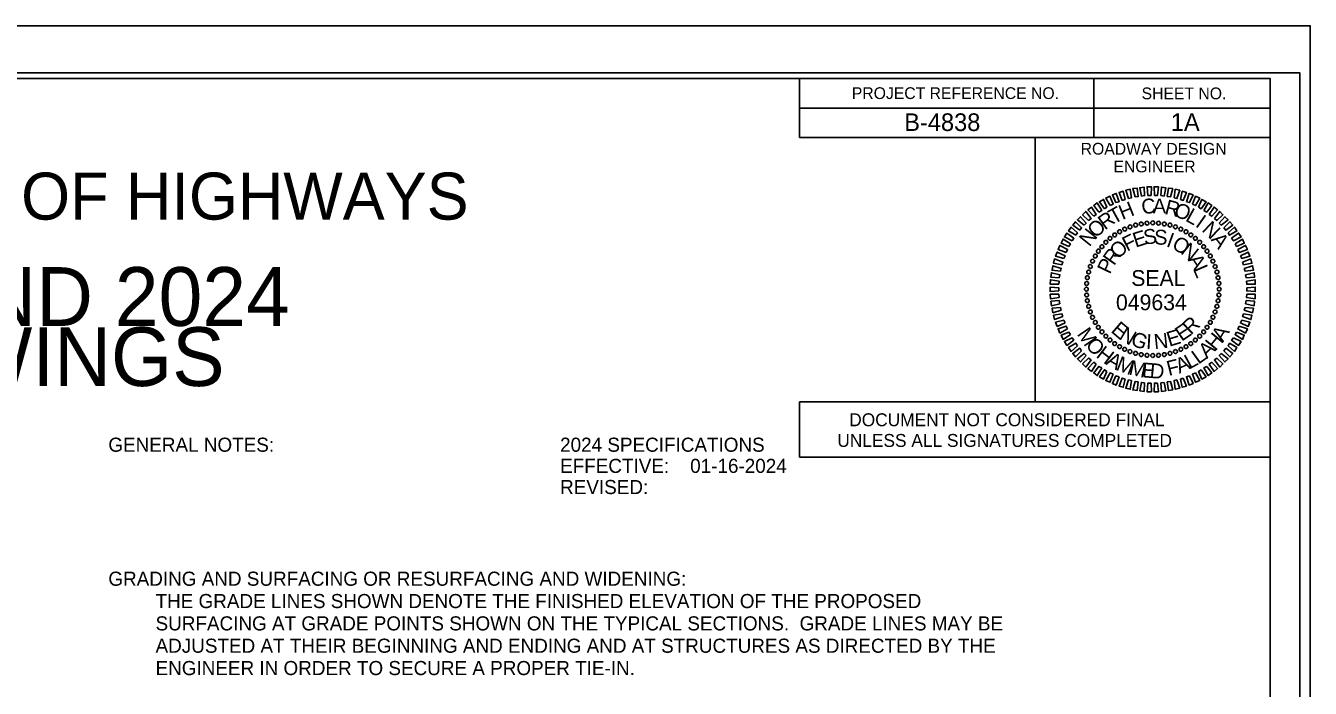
# Model space of a CAD drawing. Extents: x 775818 to 777502, y 889228 to 890323.
# Drawn here: x 776956 to 777502, y 890041 to 890323 of the extents above; entities that cross this region are included whole.
import ezdxf

# ---------------------------------------------------------------- set-up
doc = ezdxf.new("R2010")
doc.units = 0
for name, color, linetype in [('Default', 7, 'Continuous'), ('Sheet Border Standard 30in CELL', 7, 'Continuous'), ('Sheet Cutting Line CELL', 7, 'Continuous'), ('Sheet Data Field CELL', 7, 'Continuous'), ('Sheet Data Text CELL', 7, 'Continuous'), ('Sheet Plan CELL', 7, 'Continuous'), ('Sheet Plot Border Inside CELL', 7, 'Continuous'), ('Sheet Plot Border Outside CELL', 7, 'Continuous'), ('Sheet Professional Seal CELL', 7, 'Continuous'), ('Sheet Sticker Exception Certification CELL', 7, 'Continuous'), ('Sheet Symbology CELL', 7, 'Continuous')]:
    doc.layers.add(name, color=color, linetype=linetype)

# ---------------------------------------------------------------- blocks, each defined once
blk = doc.blocks.new('POINT_DISPLAY')
at = {"layer": 'Default'}
blk.add_line((0, 0), (0, 0), dxfattribs=at)

msp = doc.modelspace()

# ---------------------------------------------------------------- linework, layer by layer
at = {"layer": 'Sheet Cutting Line CELL'}
msp.add_line((777501.78, 890323.31), (775818.28, 890323.31), dxfattribs=at)
at = {"layer": 'Sheet Plan CELL'}
for p, q in [((777409.78, 890300.76), (777409.78, 890275.76)), ((777284.73, 890288.26), (777484.78, 890288.26)), ((777284.73, 890275.76), (777484.78, 890275.76)), ((777284.73, 890275.76), (777484.78, 890275.76)), ((777384.78, 890275.76), (777384.78, 890163.31))]:
    msp.add_line(p, q, dxfattribs=at)
for points in [[(777484.78, 890300.81), (775984.78, 890300.81), (775984.78, 889250.81), (777484.78, 889250.81)], [(777284.73, 890300.81), (777484.78, 890300.81), (777484.78, 890275.76), (777284.73, 890275.76)], [(777384.78, 890275.76), (777484.78, 890275.76), (777484.78, 890163.26), (777384.78, 890163.26)]]:
    msp.add_lwpolyline(points, close=True, dxfattribs=at)
at = {"layer": 'Sheet Plot Border Inside CELL'}
msp.add_lwpolyline([(775831.28, 889248.31), (777497.28, 889248.31), (777497.28, 890303.31), (775831.28, 890303.31)], close=True, dxfattribs=at)
at = {"layer": 'Sheet Plot Border Outside CELL'}
msp.add_lwpolyline([(775818.28, 889228.31), (777501.78, 889228.31), (777501.78, 890323.31), (775818.28, 890323.31)], close=True, dxfattribs=at)
at = {"layer": 'Sheet Professional Seal CELL'}
for points in [[(777416.71, 890246.8), (777414.85, 890249.95), (777416.6, 890250.74), (777417.95, 890247.36)], [(777419.18, 890248.04), (777417.67, 890251.3), (777419.29, 890251.97), (777420.53, 890248.43)], [(777421.88, 890248.99), (777420.53, 890252.37), (777422.28, 890252.87), (777423.06, 890249.39)], [(777424.58, 890249.78), (777423.34, 890253.32), (777425.26, 890253.72), (777425.76, 890250.06)], [(777427.28, 890250.46), (777426.33, 890254), (777428.18, 890254.22), (777428.63, 890250.62)], [(777429.98, 890250.85), (777429.31, 890254.39), (777431.16, 890254.67), (777431.33, 890251.02)], [(777432.79, 890251.13), (777432.4, 890254.79), (777434.26, 890254.79), (777434.14, 890251.13)], [(777435.5, 890251.13), (777435.38, 890254.79), (777437.24, 890254.79), (777436.84, 890251.13)], [(777438.31, 890251.02), (777438.48, 890254.67), (777440.33, 890254.39), (777439.66, 890250.85)], [(777441.01, 890250.62), (777441.46, 890254.22), (777443.31, 890254), (777442.35, 890250.46)], [(777443.87, 890250.06), (777444.38, 890253.72), (777446.29, 890253.32), (777445.06, 890249.78)], [(777446.57, 890249.39), (777447.36, 890252.87), (777449.1, 890252.37), (777447.76, 890248.99)], [(777449.1, 890248.43), (777450.34, 890251.97), (777451.97, 890251.3), (777450.46, 890248.04)], [(777451.69, 890247.36), (777453.04, 890250.74), (777454.79, 890249.95), (777452.93, 890246.8)], [(777407.54, 890240.5), (777405.01, 890242.92), (777406.36, 890244.27), (777408.61, 890241.29)], [(777409.73, 890242.24), (777407.26, 890244.94), (777408.78, 890246.12), (777410.8, 890243.03)], [(777411.87, 890243.99), (777409.73, 890246.8), (777411.2, 890247.92), (777413.11, 890244.66)], [(777414.29, 890245.45), (777412.15, 890248.43), (777413.9, 890249.39), (777415.36, 890246.12)], [(777454.28, 890246.12), (777455.74, 890249.39), (777457.49, 890248.43), (777455.35, 890245.45)], [(777456.53, 890244.66), (777458.44, 890247.92), (777459.9, 890246.8), (777457.77, 890243.99)], [(777458.84, 890243.03), (777460.86, 890246.12), (777462.38, 890244.94), (777459.9, 890242.24)], [(777461.03, 890241.29), (777463.28, 890244.27), (777464.63, 890242.92), (777462.1, 890240.5)], [(777403.77, 890236.28), (777400.79, 890238.48), (777402.03, 890239.94), (777404.56, 890237.35)], [(777405.69, 890238.48), (777402.82, 890240.73), (777404.17, 890242.07), (777406.58, 890239.37)], [(777463.05, 890239.37), (777465.47, 890242.07), (777466.82, 890240.73), (777463.95, 890238.48)], [(777465.08, 890237.35), (777467.61, 890239.94), (777468.85, 890238.48), (777465.87, 890236.28)], [(777400.51, 890231.84), (777397.3, 890233.47), (777398.37, 890235.1), (777401.35, 890232.91)], [(777402.14, 890234.14), (777399.05, 890236), (777400.12, 890237.63), (777402.82, 890235.21)], [(777466.82, 890235.21), (777469.52, 890237.63), (777470.59, 890236), (777467.5, 890234.14)], [(777468.29, 890232.91), (777471.27, 890235.1), (777472.34, 890233.47), (777469.13, 890231.84)], [(777398.09, 890226.83), (777394.6, 890228.07), (777395.39, 890229.81), (777398.65, 890228.07)], [(777399.16, 890229.42), (777395.95, 890230.77), (777396.74, 890232.51), (777399.83, 890230.49)], [(777469.8, 890230.49), (777472.9, 890232.51), (777473.68, 890230.77), (777470.48, 890229.42)], [(777470.98, 890228.07), (777474.25, 890229.81), (777475.03, 890228.07), (777471.55, 890226.83)], [(777396.23, 890221.6), (777392.69, 890222.28), (777393.09, 890224.13), (777396.63, 890222.78)], [(777397.02, 890224.3), (777393.54, 890225.26), (777394.21, 890227), (777397.59, 890225.48)], [(777472.05, 890225.48), (777475.43, 890227), (777476.1, 890225.26), (777472.62, 890224.3)], [(777473.01, 890222.78), (777476.55, 890224.13), (777476.95, 890222.28), (777473.4, 890221.6)], [(777395.11, 890216.03), (777391.51, 890216.31), (777391.74, 890218.23), (777395.39, 890217.38)], [(777395.56, 890218.9), (777392.02, 890219.29), (777392.41, 890221.21), (777395.95, 890220.08)], [(777473.68, 890220.08), (777477.23, 890221.21), (777477.62, 890219.3), (777474.08, 890218.9)], [(777474.25, 890217.38), (777477.9, 890218.23), (777478.13, 890216.31), (777474.53, 890216.03)], [(777394.89, 890213.33), (777391.23, 890213.33), (777391.34, 890215.24), (777395, 890214.68)], [(777394.89, 890210.52), (777391.23, 890210.24), (777391.23, 890212.15), (777394.89, 890211.87)], [(777474.64, 890214.68), (777478.3, 890215.25), (777478.41, 890213.33), (777474.75, 890213.33)], [(777474.75, 890211.87), (777478.41, 890212.15), (777478.41, 890210.24), (777474.75, 890210.52)], [(777395, 890207.71), (777391.34, 890207.15), (777391.23, 890209.06), (777394.89, 890209.06)], [(777395.39, 890205.01), (777391.74, 890204.17), (777391.51, 890206.08), (777395.11, 890206.36)], [(777474.53, 890206.36), (777478.13, 890206.08), (777477.9, 890204.17), (777474.25, 890205.01)], [(777474.75, 890209.06), (777478.41, 890209.06), (777478.3, 890207.15), (777474.64, 890207.71)], [(777395.95, 890202.31), (777392.41, 890201.18), (777392.02, 890203.1), (777395.56, 890203.49)], [(777396.63, 890199.61), (777393.09, 890198.26), (777392.69, 890200.12), (777396.23, 890200.79)], [(777473.4, 890200.79), (777476.95, 890200.12), (777476.55, 890198.26), (777473.01, 890199.61)], [(777474.08, 890203.49), (777477.62, 890203.1), (777477.23, 890201.18), (777473.68, 890202.31)], [(777397.59, 890196.91), (777394.21, 890195.39), (777393.54, 890197.14), (777397.02, 890198.09)], [(777398.65, 890194.32), (777395.39, 890192.58), (777394.6, 890194.32), (777398.09, 890195.56)], [(777471.55, 890195.56), (777475.03, 890194.32), (777474.25, 890192.58), (777470.98, 890194.32)], [(777472.62, 890198.09), (777476.1, 890197.14), (777475.43, 890195.39), (777472.05, 890196.91)], [(777399.84, 890191.9), (777396.74, 890189.88), (777395.95, 890191.62), (777399.16, 890192.97)], [(777401.35, 890189.48), (777398.37, 890187.29), (777397.3, 890188.92), (777400.51, 890190.55)], [(777469.13, 890190.56), (777472.34, 890188.92), (777471.27, 890187.29), (777468.29, 890189.49)], [(777470.48, 890192.97), (777473.68, 890191.62), (777472.9, 890189.88), (777469.8, 890191.9)], [(777402.82, 890187.18), (777400.12, 890184.76), (777399.05, 890186.39), (777402.14, 890188.25)], [(777404.56, 890185.04), (777402.03, 890182.45), (777400.79, 890183.92), (777403.77, 890186.11)], [(777406.58, 890183.02), (777404.17, 890180.32), (777402.82, 890181.67), (777405.69, 890183.92)], [(777463.95, 890183.92), (777466.82, 890181.67), (777465.47, 890180.32), (777463.06, 890183.02)], [(777465.87, 890186.11), (777468.85, 890183.92), (777467.61, 890182.45), (777465.08, 890185.04)], [(777467.5, 890188.25), (777470.59, 890186.39), (777469.52, 890184.76), (777466.82, 890187.18)], [(777408.61, 890181.11), (777406.36, 890178.12), (777405.01, 890179.47), (777407.54, 890181.89)], [(777410.8, 890179.36), (777408.78, 890176.27), (777407.26, 890177.45), (777409.73, 890180.15)], [(777459.9, 890180.15), (777462.38, 890177.45), (777460.86, 890176.27), (777458.84, 890179.36)], [(777462.1, 890181.89), (777464.63, 890179.47), (777463.28, 890178.12), (777461.03, 890181.11)], [(777413.11, 890177.73), (777411.2, 890174.47), (777409.73, 890175.59), (777411.87, 890178.4)], [(777415.36, 890176.27), (777413.9, 890173.01), (777412.15, 890173.96), (777414.29, 890176.94)], [(777417.95, 890175.03), (777416.6, 890171.66), (777414.85, 890172.44), (777416.71, 890175.59)], [(777420.53, 890173.96), (777419.3, 890170.42), (777417.67, 890171.09), (777419.18, 890174.36)], [(777423.06, 890173.01), (777422.28, 890169.52), (777420.53, 890170.03), (777421.88, 890173.4)], [(777447.76, 890173.4), (777449.11, 890170.03), (777447.36, 890169.52), (777446.57, 890173.01)], [(777450.46, 890174.36), (777451.97, 890171.09), (777450.34, 890170.42), (777449.1, 890173.96)], [(777452.93, 890175.59), (777454.79, 890172.44), (777453.04, 890171.66), (777451.69, 890175.03)], [(777455.35, 890176.94), (777457.49, 890173.96), (777455.74, 890173.01), (777454.28, 890176.27)], [(777457.77, 890178.4), (777459.9, 890175.59), (777458.44, 890174.47), (777456.53, 890177.73)], [(777425.76, 890172.33), (777425.26, 890168.67), (777423.35, 890169.07), (777424.58, 890172.61)], [(777428.63, 890171.77), (777428.18, 890168.17), (777426.33, 890168.39), (777427.28, 890171.94)], [(777431.33, 890171.37), (777431.16, 890167.72), (777429.31, 890168), (777429.98, 890171.54)], [(777434.15, 890171.26), (777434.26, 890167.61), (777432.4, 890167.61), (777432.79, 890171.26)], [(777436.84, 890171.26), (777437.24, 890167.61), (777435.38, 890167.61), (777435.5, 890171.26)], [(777439.66, 890171.54), (777440.33, 890168), (777438.48, 890167.72), (777438.31, 890171.37)], [(777442.36, 890171.94), (777443.31, 890168.39), (777441.46, 890168.17), (777441.01, 890171.77)], [(777445.06, 890172.61), (777446.29, 890169.07), (777444.38, 890168.67), (777443.87, 890172.33)]]:
    msp.add_lwpolyline(points, close=True, dxfattribs=at)
for centre, major_axis in [((777425.16, 890237.72), (-0.277, 0.761)), ((777427.51, 890238.46), (-0.21, 0.782)), ((777429.91, 890238.99), (-0.141, 0.798)), ((777432.35, 890239.31), (-0.071, 0.807)), ((777434.81, 890239.42), (0, 0.81)), ((777437.27, 890239.31), (0.071, 0.807)), ((777439.71, 890238.99), (0.141, 0.798)), ((777442.11, 890238.46), (0.21, 0.782)), ((777444.46, 890237.72), (0.277, 0.761)), ((777416.68, 890232.82), (-0.521, 0.62)), ((777418.63, 890234.32), (-0.465, 0.663)), ((777420.71, 890235.64), (-0.405, 0.701)), ((777422.89, 890236.78), (-0.342, 0.734)), ((777446.74, 890236.78), (0.342, 0.734)), ((777448.92, 890235.64), (0.405, 0.701)), ((777450.99, 890234.32), (0.465, 0.663)), ((777452.95, 890232.82), (0.521, 0.62)), ((777411.7, 890227.39), (-0.663, 0.465)), ((777413.2, 890229.34), (-0.62, 0.521)), ((777414.86, 890231.16), (-0.573, 0.573)), ((777454.76, 890231.16), (0.573, 0.573)), ((777456.42, 890229.34), (0.62, 0.521)), ((777457.92, 890227.39), (0.663, 0.465)), ((777409.24, 890223.13), (-0.734, 0.342)), ((777410.38, 890225.31), (-0.701, 0.405)), ((777459.25, 890225.31), (0.701, 0.405)), ((777460.38, 890223.13), (0.734, 0.342)), ((777407.03, 890216.11), (-0.798, 0.141)), ((777407.56, 890218.51), (-0.782, 0.21)), ((777408.3, 890220.86), (-0.761, 0.277)), ((777461.32, 890220.86), (0.761, 0.277)), ((777462.06, 890218.51), (0.782, 0.21)), ((777462.6, 890216.11), (0.798, 0.141)), ((777406.6, 890211.21), (-0.81, 0)), ((777406.71, 890213.66), (-0.807, 0.071)), ((777462.92, 890213.67), (0.807, 0.071)), ((777463.03, 890211.21), (0.81, 0)), ((777406.71, 890208.75), (-0.807, -0.071)), ((777407.03, 890206.31), (-0.798, -0.141)), ((777462.6, 890206.31), (0.798, -0.141)), ((777462.92, 890208.75), (0.807, -0.071)), ((777407.56, 890203.9), (-0.782, -0.21)), ((777408.3, 890201.56), (-0.761, -0.277)), ((777461.32, 890201.56), (0.761, -0.277)), ((777462.06, 890203.9), (0.782, -0.21)), ((777409.24, 890199.28), (-0.734, -0.342)), ((777410.38, 890197.1), (-0.701, -0.405)), ((777411.7, 890195.02), (-0.663, -0.465)), ((777457.92, 890195.02), (0.663, -0.465)), ((777459.25, 890197.1), (0.701, -0.405)), ((777460.38, 890199.28), (0.734, -0.342)), ((777413.2, 890193.07), (-0.62, -0.521)), ((777414.86, 890191.26), (-0.573, -0.573)), ((777416.68, 890189.59), (-0.521, -0.62)), ((777452.95, 890189.59), (0.521, -0.62)), ((777454.76, 890191.26), (0.573, -0.573)), ((777456.42, 890193.07), (0.62, -0.521)), ((777418.63, 890188.1), (-0.465, -0.663)), ((777420.71, 890186.77), (-0.405, -0.701)), ((777422.89, 890185.64), (-0.342, -0.734)), ((777425.16, 890184.7), (-0.277, -0.761)), ((777427.51, 890183.96), (-0.21, -0.782)), ((777429.91, 890183.42), (-0.141, -0.798)), ((777432.35, 890183.1), (-0.071, -0.807)), ((777437.27, 890183.1), (0.071, -0.807)), ((777439.71, 890183.42), (0.141, -0.798)), ((777442.11, 890183.96), (0.21, -0.782)), ((777444.46, 890184.7), (0.277, -0.761)), ((777446.74, 890185.64), (0.342, -0.734)), ((777448.92, 890186.77), (0.405, -0.701)), ((777450.99, 890188.1), (0.465, -0.663)), ((777434.81, 890182.99), (0, -0.81))]:
    msp.add_ellipse(centre, major_axis=major_axis, ratio=0.999708, dxfattribs=at)
at = {"layer": 'Sheet Sticker Exception Certification CELL'}
for p, q in [((777284.75, 890139.77), (777284.75, 890163.27)), ((777284.75, 890163.27), (777484.78, 890163.27)), ((777484.78, 890163.26), (777484.78, 890139.76)), ((777484.78, 890139.77), (777284.75, 890139.77))]:
    msp.add_line(p, q, dxfattribs=at)

# ---------------------------------------------------------------- block references
at = {"layer": 'Sheet Professional Seal CELL', "xscale": 69.00008201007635, "yscale": 69.00008201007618, "rotation": 0.0004298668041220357}
for p in [(777429.93, 890238.98), (777432.34, 890239.32), (777434.82, 890239.43), (777437.29, 890239.32), (777439.71, 890238.98), (777418.62, 890234.31), (777420.7, 890235.66), (777422.9, 890236.79), (777425.15, 890237.74), (777427.51, 890238.48), (777442.13, 890238.48), (777444.49, 890237.74), (777446.74, 890236.79), (777448.94, 890235.66), (777451.02, 890234.31), (777413.17, 890229.36), (777414.85, 890231.16), (777416.65, 890232.85), (777452.99, 890232.85), (777454.79, 890231.16), (777456.47, 890229.36), (777409.23, 890223.12), (777410.35, 890225.31), (777411.7, 890227.39), (777457.94, 890227.4), (777459.29, 890225.31), (777460.41, 890223.12), (777407.54, 890218.51), (777408.27, 890220.87), (777461.37, 890220.87), (777462.1, 890218.51), (777406.7, 890213.67), (777407.03, 890216.09), (777462.94, 890213.67), (777406.58, 890211.2), (777406.7, 890208.72), (777407.03, 890206.3), (777434.82, 890211.2), (777462.6, 890206.3), (777462.94, 890208.72), (777463.05, 890211.2), (777407.54, 890203.88), (777408.27, 890201.52), (777461.37, 890201.52), (777462.1, 890203.89), (777411.7, 890195), (777457.94, 890195), (777459.29, 890197.08), (777460.41, 890199.27), (777413.17, 890193.03), (777414.85, 890191.23), (777416.65, 890189.54), (777452.99, 890189.54), (777454.79, 890191.23), (777456.47, 890193.03), (777418.62, 890188.08), (777420.7, 890186.73), (777422.9, 890185.61), (777425.15, 890184.65), (777427.51, 890183.92), (777442.13, 890183.92), (777444.49, 890184.65), (777446.74, 890185.61), (777448.94, 890186.73), (777451.02, 890188.08), (777429.93, 890183.41), (777432.34, 890183.07), (777434.82, 890182.96), (777437.29, 890183.07), (777439.71, 890183.41)]:
    msp.add_blockref('POINT_DISPLAY', p, dxfattribs=at)

# ---------------------------------------------------------------- texts
at = {"layer": 'Sheet Border Standard 30in CELL'}
msp.add_text('ENGINEER', height=4.999, rotation=0, dxfattribs=at).set_placement((777418.12, 890260.92))
at = {"layer": 'Sheet Data Field CELL'}
for s, height, p in [('B-4838', 7.5, (777329.2, 890278.51)), ('1A ', 7.5, (777442.5, 890278.56)), ('INDEX OF SHEETS, GENERAL NOTES AND 2024 ', 25, (776300.8, 890195.61)), ('ROADWAY ENGLISH STANDARD DRAWINGS', 25, (776325.23, 890170.03))]:
    msp.add_text(s, height=height, dxfattribs=at).set_placement(p)
at = {"layer": 'Sheet Data Text CELL'}
for s, p in [('GENERAL NOTES:', (776990.94, 890142.07)), ('2024 SPECIFICATIONS', (777182.94, 890142.07)), ('EFFECTIVE:    01-16-2024', (777182.94, 890133.07)), ('REVISED:', (777182.94, 890124.07)), ('GRADING AND SURFACING OR RESURFACING AND WIDENING:  ', (776990.94, 890085.07)), ('         THE GRADE LINES SHOWN DENOTE THE FINISHED ELEVATION OF THE PROPOSED', (776990.94, 890075.57)), ('         SURFACING AT GRADE POINTS SHOWN ON THE TYPICAL SECTIONS.  GRADE LINES MAY BE  ', (776990.94, 890066.07)), ('         ADJUSTED AT THEIR BEGINNING AND ENDING AND AT STRUCTURES AS DIRECTED BY THE ', (776990.94, 890056.57)), ('         ENGINEER IN ORDER TO SECURE A PROPER TIE-IN.  ', (776990.94, 890047.07))]:
    msp.add_text(s, height=6, dxfattribs=at).set_placement(p)
at = {"layer": 'Sheet Plan CELL'}
for s, height, p in [('PROJECT REFERENCE NO.', 5.0001, (777306.93, 890292.11)), ('SHEET NO.', 5, (777430.08, 890292.01)), ('ROADWAY DESIGN', 5.0001, (777404.18, 890268.46))]:
    msp.add_text(s, height=height, dxfattribs=at).set_placement(p)
at = {"layer": 'Sheet Professional Seal CELL'}
for s, height, rotation, p in [('C', 6.34, 7.2203, (777430.39, 890243.03)), ('A', 6.34, 0.0207, (777434.83, 890243.42)), ('T', 6.34, 28.8202, (777418.23, 890238.7)), ('H', 6.34, 21.6199, (777421.89, 890240.61)), ('R', 6.34, 345.6215, (777439.55, 890243.31)), ('O', 6.34, 338.4216, (777443.33, 890242.52)), ('L', 6.34, 331.2213, (777448.33, 890240.49)), ('O', 6.34, 43.2222, (777410.65, 890232.64)), ('R', 6.34, 36.0209, (777414.47, 890236.17)), ('I', 6.34, 324.781, (777452.58, 890238.15)), ('N', 6.34, 316.8193, (777455.35, 890236.16)), ('N', 6.34, 51.1609, (777407.88, 890228.97)), ('F', 6.34, 26.9675, (777423.9, 890227.11)), ('E', 6.34, 17.6115, (777427.5, 890228.85)), ('S', 6.34, 8.256, (777431.33, 890230.09)), ('S', 6.34, 358.9008, (777435.38, 890230.21)), ('I', 6.34, 340.19, (777440.23, 890229.53)), ('O', 6.34, 330.8339, (777442.54, 890228.74)), ('A', 6.34, 308.0625, (777459.31, 890232.24)), ('R', 6.34, 55.0401, (777418.35, 890220.94)), ('O', 6.34, 45.6817, (777420.26, 890223.75)), ('N', 6.34, 321.477, (777446.3, 890226.6)), ('P', 6.34, 64.3993, (777416.6, 890217.28)), ('A', 6.34, 302.7607, (777449.56, 890223.73)), ('SEAL', 6.747, 0.0004, (777425.68, 890212.6)), ('L', 6.34, 293.4013, (777451.81, 890219.85)), ('049634', 6.749, 0.0004, (777419.18, 890202.25)), ('M', 6.34, 304.4111, (777402.38, 890192.13)), ('E', 6.34, 319.2773, (777416.7, 890193.26)), ('N', 6.34, 328.6344, (777420.09, 890190.27)), ('E', 6.34, 34.1245, (777447.08, 890188.81)), ('R', 6.34, 43.4818, (777451.03, 890191.52)), ('O', 6.34, 313.5072, (777405.9, 890187.08)), ('G', 6.34, 339.5036, (777425.04, 890187.59)), ('I', 6.34, 356.7016, (777431.85, 890185.83)), ('N', 6.34, 6.0568, (777435.61, 890185.72)), ('E', 6.34, 16.9673, (777441.84, 890186.68)), ('H', 6.34, 50.6835, (777461.46, 890184.66)), ('A', 6.34, 57.8787, (777464.72, 890188.44)), ('H', 6.34, 322.6656, (777410.36, 890182.54)), ('L', 6.34, 35.694, (777454.23, 890179.06)), ('A', 6.34, 42.8793, (777457.81, 890181.47)), ('A', 6.34, 330.5496, (777414.55, 890179.42)), ('M', 6.34, 338.9258, (777418.82, 890177.05)), ('M', 6.34, 348.0168, (777424.36, 890174.96)), ('E', 6.34, 355.1435, (777430.07, 890173.78)), ('D', 6.34, 355.1435, (777433.38, 890173.5)), ('F', 6.34, 14.0832, (777441.6, 890174.3)), ('A', 6.34, 23.9839, (777446.13, 890175.26)), ('L', 6.34, 28.7287, (777450.47, 890177.09))]:
    msp.add_text(s, height=height, rotation=rotation, dxfattribs=at).set_placement(p)
at = {"layer": 'Sheet Sticker Exception Certification CELL'}
for s, p in [('DOCUMENT NOT CONSIDERED FINAL', (777305.82, 890152.93)), ('UNLESS ALL SIGNATURES COMPLETED', (777300.75, 890144.13))]:
    msp.add_text(s, height=5.5, dxfattribs=at).set_placement(p)
at = {"layer": 'Sheet Symbology CELL'}
msp.add_text('STATE OF NORTH CAROLINA, DIVISION OF HIGHWAYS', height=20, dxfattribs=at).set_placement((776436.75, 890240.81))

doc.saveas('drawing.dxf')
